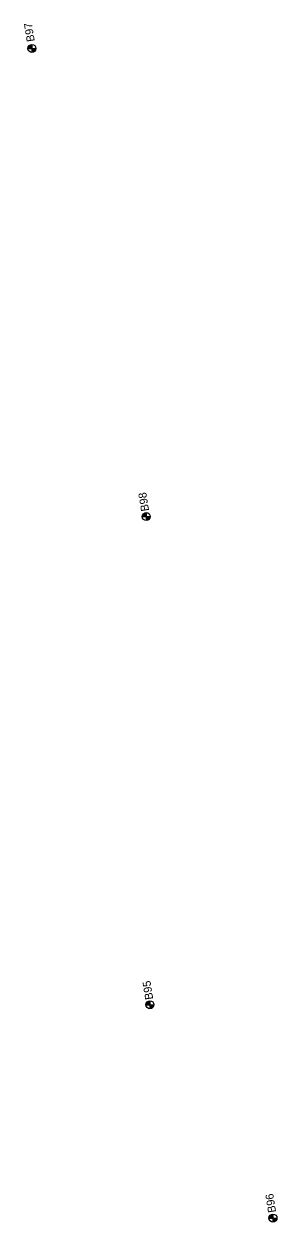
# Model space of a CAD drawing. Extents: x 335726 to 369746, y 119154 to 200788.
# Drawn here: x 355992 to 356308, y 180354 to 181852 of the extents above; entities that cross this region are included whole.
import ezdxf

# ---------------------------------------------------------------- set-up
doc = ezdxf.new("R2010")
doc.units = 0
for name, color, linetype in [('E_SOIL_BORE1 [KAPUR_CADDS_LEVELS]', 7, 'Continuous'), ('E_SOIL_BORE2 [KAPUR_CADDS_LEVELS]', 7, 'Continuous'), ('P_MARK', 7, 'Continuous')]:
    doc.layers.add(name, color=color, linetype=linetype)

msp = doc.modelspace()

# ---------------------------------------------------------------- linework, layer by layer
at = {"layer": 'P_MARK'}
for p, q in [((356002.1, 181826), (356002.1, 181816)), ((355997.1, 181821), (356007.1, 181821)), ((356145, 181241), (356145, 181231)), ((356140, 181236), (356150, 181236)), ((356144.6, 180626), (356154.6, 180626)), ((356149.6, 180631), (356149.6, 180621)), ((356298.3, 180359.4), (356308.3, 180359.4)), ((356303.3, 180364.4), (356303.3, 180354.4))]:
    msp.add_line(p, q, dxfattribs=at)
for centre in [(356002.1, 181821), (356145, 181236), (356149.6, 180626), (356303.3, 180359.4)]:
    msp.add_circle(centre, 5, dxfattribs=at)
for centre, radius, start, end in [((356002.1, 181821), 4.5, 89.9869, 179.9869), ((356002.1, 181821), 4, 89.9869, 179.9869), ((356002.1, 181821), 3.5, 89.9869, 179.9869), ((356002.1, 181821), 3, 89.9869, 179.9869), ((356002.1, 181821), 2.5, 89.9869, 179.9869), ((356002.1, 181821), 2, 89.9869, 179.9869), ((356002.1, 181821), 1.5, 89.9869, 179.9869), ((356002.1, 181821), 1, 89.9869, 179.9869), ((356002.1, 181821), 0.5, 89.9869, 179.9869), ((356002.1, 181821), 4.5, 269.9869, 359.9869), ((356002.1, 181821), 4, 269.9869, 359.9869), ((356002.1, 181821), 3.5, 269.9869, 359.9869), ((356002.1, 181821), 3, 269.9869, 359.9869), ((356002.1, 181821), 2.5, 269.9869, 359.9869), ((356002.1, 181821), 2, 269.9869, 359.9869), ((356002.1, 181821), 1.5, 269.9869, 359.9869), ((356002.1, 181821), 1, 269.9869, 359.9869), ((356002.1, 181821), 0.5, 269.9869, 359.9869), ((356145, 181236), 4.5, 89.9869, 179.9869), ((356145, 181236), 4, 89.9869, 179.9869), ((356145, 181236), 3.5, 89.9869, 179.9869), ((356145, 181236), 3, 89.9869, 179.9869), ((356145, 181236), 2.5, 89.9869, 179.9869), ((356145, 181236), 2, 89.9869, 179.9869), ((356145, 181236), 1.5, 89.9869, 179.9869), ((356145, 181236), 1, 89.9869, 179.9869), ((356145, 181236), 0.5, 89.9869, 179.9869), ((356145, 181236), 4.5, 269.9869, 359.9869), ((356145, 181236), 4, 269.9869, 359.9869), ((356145, 181236), 3.5, 269.9869, 359.9869), ((356145, 181236), 3, 269.9869, 359.9869), ((356145, 181236), 2.5, 269.9869, 359.9869), ((356145, 181236), 2, 269.9869, 359.9869), ((356145, 181236), 1.5, 269.9869, 359.9869), ((356145, 181236), 1, 269.9869, 359.9869), ((356145, 181236), 0.5, 269.9869, 359.9869), ((356149.6, 180626), 4.5, 89.9869, 179.9869), ((356149.6, 180626), 4, 89.9869, 179.9869), ((356149.6, 180626), 3.5, 89.9869, 179.9869), ((356149.6, 180626), 3, 89.9869, 179.9869), ((356149.6, 180626), 2.5, 89.9869, 179.9869), ((356149.6, 180626), 2, 89.9869, 179.9869), ((356149.6, 180626), 1.5, 89.9869, 179.9869), ((356149.6, 180626), 1, 89.9869, 179.9869), ((356149.6, 180626), 0.5, 89.9869, 179.9869), ((356149.6, 180626), 4.5, 269.9869, 359.9869), ((356149.6, 180626), 4, 269.9869, 359.9869), ((356149.6, 180626), 3.5, 269.9869, 359.9869), ((356149.6, 180626), 3, 269.9869, 359.9869), ((356149.6, 180626), 2.5, 269.9869, 359.9869), ((356149.6, 180626), 2, 269.9869, 359.9869), ((356149.6, 180626), 1.5, 269.9869, 359.9869), ((356149.6, 180626), 1, 269.9869, 359.9869), ((356149.6, 180626), 0.5, 269.9869, 359.9869), ((356303.3, 180359.4), 4.5, 89.9869, 179.9869), ((356303.3, 180359.4), 4, 89.9869, 179.9869), ((356303.3, 180359.4), 3.5, 89.9869, 179.9869), ((356303.3, 180359.4), 3, 89.9869, 179.9869), ((356303.3, 180359.4), 2.5, 89.9869, 179.9869), ((356303.3, 180359.4), 2, 89.9869, 179.9869), ((356303.3, 180359.4), 1.5, 89.9869, 179.9869), ((356303.3, 180359.4), 1, 89.9869, 179.9869), ((356303.3, 180359.4), 0.5, 89.9869, 179.9869), ((356303.3, 180359.4), 4.5, 269.9869, 359.9869), ((356303.3, 180359.4), 4, 269.9869, 359.9869), ((356303.3, 180359.4), 3.5, 269.9869, 359.9869), ((356303.3, 180359.4), 3, 269.9869, 359.9869), ((356303.3, 180359.4), 2.5, 269.9869, 359.9869), ((356303.3, 180359.4), 2, 269.9869, 359.9869), ((356303.3, 180359.4), 1.5, 269.9869, 359.9869), ((356303.3, 180359.4), 1, 269.9869, 359.9869), ((356303.3, 180359.4), 0.5, 269.9869, 359.9869)]:
    msp.add_arc(centre, radius, start, end, dxfattribs=at)

# ---------------------------------------------------------------- texts
at = {"layer": 'E_SOIL_BORE1 [KAPUR_CADDS_LEVELS]'}
for s, p in [('B97', (356005.7, 181830.2)), ('B98', (356148.5, 181243.4)), ('B95', (356153.7, 180633.1))]:
    msp.add_text(s, height=10, rotation=98.957, dxfattribs=at).set_placement(p)
at = {"layer": 'E_SOIL_BORE2 [KAPUR_CADDS_LEVELS]'}
msp.add_text('B96', height=10, rotation=98.957, dxfattribs=at).set_placement((356307.2, 180367))

doc.saveas('drawing.dxf')
